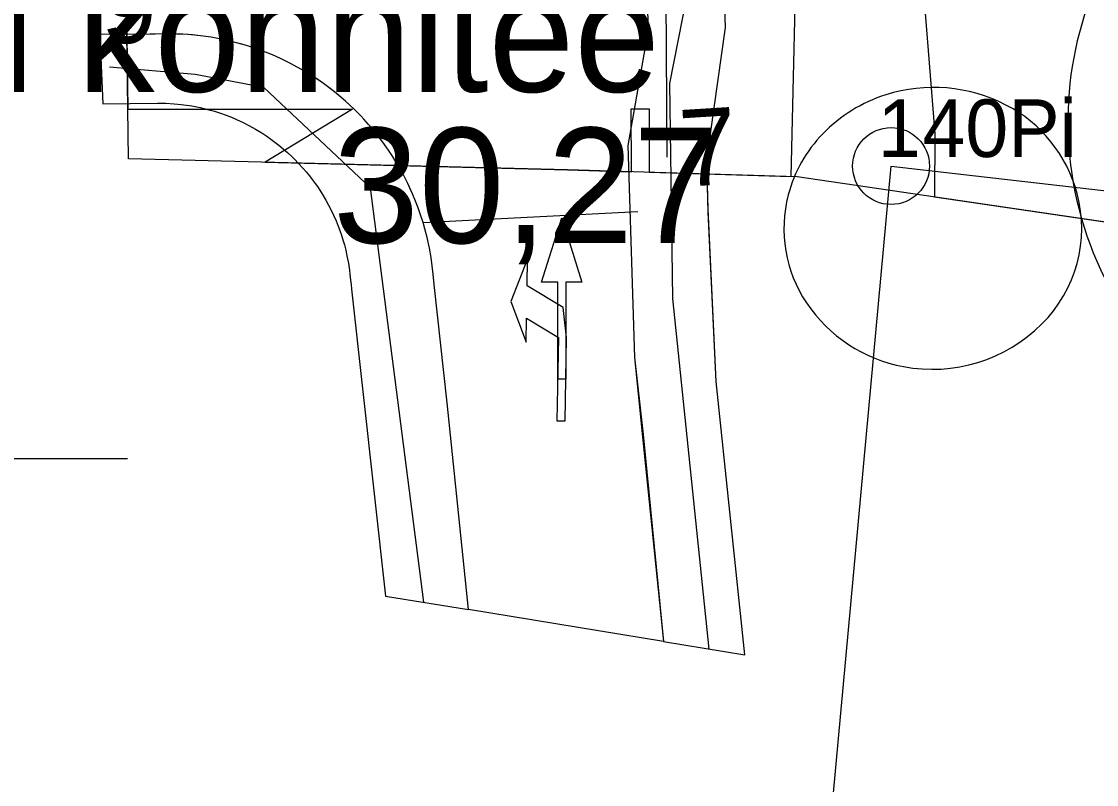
# Model space of a CAD drawing. Extents: x 738423 to 738903, y 6589762 to 6590172.
# Drawn here: x 738562.92 to 738590.9, y 6589849.85 to 6589869.71 of the extents above; entities that cross this region are included whole.
import ezdxf

# ---------------------------------------------------------------- set-up
doc = ezdxf.new("R2010")
doc.units = 0
for name, color, linetype in [('_1927_koordin_punktid_nr', 7, 'Continuous'), ('_1927_krundi_piir', 7, 'Continuous'), ('_a_olol_maapind', 7, 'Continuous'), ('a_', 7, 'Continuous'), ('a_dendro_III_vk_puu', 7, 'Continuous'), ('a_dendro_IV_vk_puu', 7, 'Continuous'), ('a_dendro_puu_nr', 7, 'Continuous'), ('Default', 7, 'Continuous'), ('plan_ala', 7, 'Continuous'), ('v_dp_jalak_liikumine', 7, 'Continuous'), ('v_olol_kitsendus_tehnov', 7, 'Continuous'), ('v_olol_sõidusuunad', 7, 'Continuous'), ('v_olol_transp_jjt_jalg', 7, 'Continuous'), ('v_olol_transp_tee', 7, 'Continuous')]:
    doc.layers.add(name, color=color, linetype=linetype)

# ---------------------------------------------------------------- blocks, each defined once
blk = doc.blocks.new('_U589')
at = {"layer": 'Default'}
for centre, radius, start, end in [((-3.0332052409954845e-05, -0.002338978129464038), 0.01836532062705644, 93.86605779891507, 141.50719662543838), ((-4.742218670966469e-05, -0.0020860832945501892), 0.018111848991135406, 48.095809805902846, 93.86605779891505), ((0.00495080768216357, 0.003483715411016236), 0.010628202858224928, 347.0797159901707, 48.09580980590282), ((-0.006053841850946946, 0.0024511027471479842), 0.01066937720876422, 141.5071966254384, 205.50153110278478), ((0.003081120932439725, 0.003912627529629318), 0.012546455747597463, 307.30050710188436, 347.0797159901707), ((-0.004183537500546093, 0.0033432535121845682), 0.012741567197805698, 205.50153110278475, 244.5264522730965), ((-0.0011840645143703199, 0.009511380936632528), 0.019584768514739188, 275.69820016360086, 307.30050710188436), ((-0.0011946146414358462, 0.009617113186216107), 0.019691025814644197, 244.52645227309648, 275.69820016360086)]:
    blk.add_arc(centre, radius, start, end, dxfattribs=at)
blk = doc.blocks.new('_U590')
at = {"layer": 'Default'}
for centre, radius, start, end in [((-0.0016871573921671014, -0.001799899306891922), 0.00692826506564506, 79.6495714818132, 128.1559824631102), ((-0.0017312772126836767, -0.002041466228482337), 0.007173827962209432, 50.05210261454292, 79.6495714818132), ((-0.0011461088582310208, -0.002488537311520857), 0.007804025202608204, 128.15598246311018, 173.69638815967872), ((-0.0022149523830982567, -0.0026189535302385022), 0.007927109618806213, 21.92646920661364, 50.052102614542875), ((-0.002480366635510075, -0.0027257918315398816), 0.008213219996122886, 337.0064535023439, 21.92646920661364), ((-0.0008438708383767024, -0.0025219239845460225), 0.0081081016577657, 173.69638815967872, 229.18747812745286), ((-0.0016395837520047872, -0.0030825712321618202), 0.007299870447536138, 289.19482591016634, 337.0064535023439), ((-0.0015500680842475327, -0.0033396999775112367), 0.0070276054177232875, 229.1874781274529, 289.1948259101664)]:
    blk.add_arc(centre, radius, start, end, dxfattribs=at)

msp = doc.modelspace()

# ---------------------------------------------------------------- linework, layer by layer
at = {"layer": '_1927_koordin_punktid_nr'}
msp.add_circle((738585.555873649, 6589865.948799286), 0.9999999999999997, dxfattribs=at)
at = {"layer": '_1927_krundi_piir'}
msp.add_line((738585.5558736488, 6589865.948799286), (738628.4452282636, 6589861.013076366), dxfattribs=at)
msp.add_lwpolyline([(738576.2192239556, 6589785.5837573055), (738579.4444540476, 6589812.005081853), (738580.8623448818, 6589823.675676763), (738581.9676572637, 6589832.801945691), (738582.8075223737, 6589836.050380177), (738585.555873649, 6589865.948799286)], dxfattribs=at)
at = {"layer": 'a_'}
for p, q in [((738579.7240658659, 6589866.182764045), (738579.6493548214, 6589878.283505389)), ((738539.292371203, 6589858.339526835), (738565.6824737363, 6589858.339526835))]:
    msp.add_line(p, q, dxfattribs=at)
at = {"layer": 'Default'}
msp.add_lwpolyline([(738579.014, 6589875.606999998), (738579.2310000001, 6589869.493000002), (738578.7019999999, 6589866.485), (738578.8769999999, 6589860.961), (738579.632728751, 6589853.570491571), (738581.7524627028, 6589853.223434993), (738581.004, 6589860.344), (738580.7943856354, 6589864.828322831), (738580.7600000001, 6589866.106), (738581.2509999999, 6589869.558000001), (738581.073, 6589874.656)], dxfattribs=at)
at = {"layer": 'plan_ala'}
msp.add_lwpolyline([(738772.2221966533, 6589837.873120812), (738583.11, 6589865.669999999), (738583.11, 6589865.669999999), (738577.13, 6589865.85), (738565.7035831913, 6589866.139410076), (738565.4500000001, 6589885.77), (738564.4932191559, 6589941.052825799), (738581.9, 6589941.1499999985), (738615.11, 6589942.169999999), (738650.0499999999, 6589943.319999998), (738691.2690631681, 6589944.800325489), (738696.0901513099, 6589944.851371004), (738713.89, 6589945.129999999), (738703.51, 6589987.789999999), (738752.8799999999, 6590000.39), (738783.1408503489, 6590007.463828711), (738767.5688789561, 6589951.87996157)], close=True, dxfattribs=at)
at = {"layer": 'v_dp_jalak_liikumine'}
msp.add_line((738573.3744552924, 6589864.476376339), (738578.9635974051, 6589864.765707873), dxfattribs=at)
for points in [[(738580.8222069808, 6589853.375742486), (738579.8731274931, 6589862.502301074), (738579.7948247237, 6589868.094183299), (738580.455907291, 6589871.452329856), (738579.9085136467, 6589877.0110812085), (738579.325053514, 6589882.302804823), (738578.6922566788, 6589901.835364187), (738578.2534358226, 6589923.78491095), (738577.7643827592, 6589940.522382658), (738578.0100246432, 6589944.392285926), (738576.7151896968, 6589950.204053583)], [(738573.3920130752, 6589854.592261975), (738572.0100758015, 6589865.3794858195), (738569.2273186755, 6589867.989252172), (738567.4426170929, 6589868.3328705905), (738565.2094625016, 6589868.519053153)]]:
    msp.add_lwpolyline(points, dxfattribs=at)
at = {"layer": 'v_olol_kitsendus_tehnov'}
for points in [[(738585.9107412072, 6589876.549701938), (738586.6978541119, 6589866.78586143), (738586.6888850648, 6589865.143953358), (738591.9451522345, 6589864.37135473)], [(738565.6046055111, 6589873.801551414), (738565.6869613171, 6589867.426156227), (738571.5336106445, 6589867.43149151), (738569.2669358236, 6589866.049156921), (738577.1299999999, 6589865.8500000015), (738578.7979030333, 6589865.799795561), (738578.7947118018, 6589867.438117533), (738579.2613153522, 6589867.438543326), (738579.2582244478, 6589865.7859397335), (738582.957333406, 6589865.674595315), (738583.1203691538, 6589872.717573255)]]:
    msp.add_lwpolyline(points, dxfattribs=at)
at = {"layer": 'v_olol_sõidusuunad'}
for points in [[(738577.5114060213, 6589862.922177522), (738577.0914062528, 6589862.922619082), (738577.0887569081, 6589860.402620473), (738576.8787570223, 6589860.402841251), (738576.8814063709, 6589862.92283986), (738576.4614066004, 6589862.923281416), (738576.9881725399, 6589864.602728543)], [(738576.0948898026, 6589863.532438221), (738575.6548239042, 6589862.420169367), (738576.0558806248, 6589861.362788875), (738576.0672058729, 6589861.992687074), (738576.8982616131, 6589861.487665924), (738576.8592524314, 6589859.318016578), (738577.0692184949, 6589859.314241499), (738577.1082276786, 6589861.483890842), (738577.017243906, 6589862.264402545), (738576.0823061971, 6589862.832551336)]]:
    msp.add_lwpolyline(points, close=True, dxfattribs=at)
at = {"layer": 'v_olol_transp_jjt_jalg'}
msp.add_lwpolyline([(738579.0140000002, 6589875.607), (738579.2310000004, 6589869.493000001), (738578.7019999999, 6589866.484999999), (738578.877, 6589860.960999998), (738579.1017005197, 6589858.959409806), (738579.632728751, 6589853.57049157), (738581.7524627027, 6589853.223434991), (738581.004, 6589860.343999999), (738580.798, 6589864.750999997), (738580.7599999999, 6589866.106), (738581.2509999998, 6589869.558000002), (738581.073, 6589874.656)], dxfattribs=at)
msp.add_lwpolyline([(738572.3946838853, 6589854.7555511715), (738574.5591009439, 6589854.401178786), (738574.004, 6589859.782999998), (738573.6600000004, 6589862.862), (738573.6395755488, 6589863.131091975), (738573.6147114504, 6589863.353287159), (738573.5837051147, 6589863.568169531), (738573.5398720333, 6589863.813214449), (738573.479722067, 6589864.0881818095), (738573.4215000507, 6589864.3137841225), (738573.3744552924, 6589864.476376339), (738573.3111121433, 6589864.6748357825), (738573.2448793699, 6589864.86300471), (738573.1786534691, 6589865.035672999), (738573.0989096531, 6589865.227154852), (738573.04262213, 6589865.353333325), (738572.9757975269, 6589865.4949414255), (738572.852584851, 6589865.736401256), (738572.7881642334, 6589865.854004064), (738572.6672425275, 6589866.061245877), (738572.5789254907, 6589866.202866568), (738572.4713293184, 6589866.365743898), (738572.3253519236, 6589866.571885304), (738572.1786709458, 6589866.764068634), (738572.0499184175, 6589866.921946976), (738571.9538094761, 6589867.03386917), (738571.8311355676, 6589867.170000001), (738571.7540000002, 6589867.251999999), (738571.5939999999, 6589867.42), (738571.4575932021, 6589867.54389603), (738571.355055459, 6589867.637076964), (738571.1835234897, 6589867.784882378), (738571.0680918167, 6589867.879011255), (738570.9216031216, 6589867.992681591), (738570.7808902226, 6589868.096115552), (738570.6347633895, 6589868.197892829), (738570.5405588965, 6589868.260602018), (738570.3556464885, 6589868.374174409), (738570.2066602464, 6589868.465681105), (738569.9079593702, 6589868.628036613), (738569.7716900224, 6589868.6945040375), (738569.6659419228, 6589868.746084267), (738569.4534425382, 6589868.840351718), (738569.2770557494, 6589868.910307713), (738569.1559594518, 6589868.958335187), (738568.9883774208, 6589869.01791195), (738568.7749243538, 6589869.08687376), (738568.6236922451, 6589869.129865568), (738568.5181900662, 6589869.159857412), (738568.2873880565, 6589869.21645726), (738568.0740578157, 6589869.261377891), (738567.8551332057, 6589869.300242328), (738567.5852627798, 6589869.338247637), (738567.3690840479, 6589869.36091705), (738567.1188560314, 6589869.378618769), (738566.9526499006, 6589869.3853465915), (738566.7632089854, 6589869.388136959), (738566.6194704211, 6589869.387216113), (738566.2617180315, 6589869.384185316), (738564.9604277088, 6589869.373161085), (738565.0397227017, 6589867.569216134), (738566.4576086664, 6589867.586150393), (738566.6749656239, 6589867.583258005), (738566.8955249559, 6589867.570641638), (738567.0760495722, 6589867.55300772), (738567.3583810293, 6589867.512055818), (738567.5766583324, 6589867.468983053), (738567.7619819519, 6589867.424388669), (738567.9448603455, 6589867.372947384), (738568.1019275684, 6589867.322687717), (738568.2531859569, 6589867.268800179), (738568.3838190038, 6589867.217782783), (738568.5203121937, 6589867.15988506), (738568.6905623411, 6589867.08081851), (738568.852538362, 6589866.9981868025), (738569.0166993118, 6589866.906638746), (738569.1751405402, 6589866.810355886), (738569.309234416, 6589866.722380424), (738569.4808044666, 6589866.600484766), (738569.6232108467, 6589866.490702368), (738569.7363210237, 6589866.3974643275), (738569.8436929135, 6589866.303612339), (738569.9671767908, 6589866.188704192), (738570.0359672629, 6589866.121201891), (738570.1273440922, 6589866.027364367), (738570.2555975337, 6589865.886901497), (738570.3343811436, 6589865.795032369), (738570.416, 6589865.694891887), (738570.4890914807, 6589865.600518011), (738570.5673997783, 6589865.493975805), (738570.6229726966, 6589865.414618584), (738570.7329121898, 6589865.247255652), (738570.8431480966, 6589865.063240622), (738570.916, 6589864.930883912), (738571.0006800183, 6589864.763904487), (738571.0452007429, 6589864.66937624), (738571.1092237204, 6589864.523585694), (738571.1641554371, 6589864.387311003), (738571.2081053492, 6589864.2690667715), (738571.2483489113, 6589864.151904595), (738571.2885087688, 6589864.024386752), (738571.3256891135, 6589863.894202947), (738571.3600628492, 6589863.760033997), (738571.3932952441, 6589863.61270181), (738571.4092725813, 6589863.533332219), (738571.4299250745, 6589863.419156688), (738571.4576571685, 6589863.233929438), (738571.4695776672, 6589863.135003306), (738571.486699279, 6589862.979918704), (738571.4996085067, 6589862.862989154), (738571.5129433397, 6589862.742204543)], close=True, dxfattribs=at)
at = {"layer": 'v_olol_transp_tee'}
msp.add_lwpolyline([(738579.0140000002, 6589875.607), (738579.2310000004, 6589869.493000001), (738578.7019999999, 6589866.484999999), (738578.877, 6589860.960999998), (738579.097, 6589858.816), (738579.632728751, 6589853.57049157), (738574.5591009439, 6589854.401178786), (738574.004, 6589859.782999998), (738573.6600000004, 6589862.862), (738573.6395755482, 6589863.131091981), (738573.6147114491, 6589863.35328717), (738573.5837051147, 6589863.568169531), (738573.5398720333, 6589863.813214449), (738573.479722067, 6589864.0881818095), (738573.4215000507, 6589864.3137841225), (738573.3744552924, 6589864.476376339), (738573.3111121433, 6589864.6748357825), (738573.2448793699, 6589864.86300471), (738573.1786534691, 6589865.035672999), (738573.0989096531, 6589865.227154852), (738572.9757975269, 6589865.4949414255), (738572.8525848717, 6589865.736401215), (738572.7266290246, 6589865.96152927), (738572.5789254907, 6589866.202866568), (738572.4713293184, 6589866.365743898), (738572.3253519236, 6589866.571885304), (738572.1786709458, 6589866.764068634), (738572.0499184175, 6589866.921946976), (738571.9538094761, 6589867.03386917), (738571.8311355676, 6589867.170000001), (738571.754, 6589867.251999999), (738571.5877808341, 6589867.42), (738571.355055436, 6589867.637076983), (738571.068091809, 6589867.879011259), (738570.7808902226, 6589868.096115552), (738570.5405588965, 6589868.260602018), (738570.2066602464, 6589868.465681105), (738569.9079594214, 6589868.628036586), (738569.6659419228, 6589868.746084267), (738569.4534425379, 6589868.840351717), (738569.1559594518, 6589868.958335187), (738568.9883774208, 6589869.01791195), (738568.7749244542, 6589869.086873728), (738568.5181900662, 6589869.159857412), (738568.2873880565, 6589869.21645726), (738568.0740578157, 6589869.261377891), (738567.8551331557, 6589869.300242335), (738567.5852627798, 6589869.338247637), (738567.2635901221, 6589869.369492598), (738566.9526499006, 6589869.3853465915), (738566.7632089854, 6589869.388136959), (738566.712, 6589869.388), (738566.6194704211, 6589869.387216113), (738566.3996066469, 6589869.385353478), (738564.9604277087, 6589869.373161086), (738564.4467826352, 6589875.534444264)], dxfattribs=at)

# ---------------------------------------------------------------- block references
at = {"layer": 'a_dendro_III_vk_puu', "xscale": 500.0000000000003, "yscale": 500.0000000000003, "rotation": 85.69234851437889}
msp.add_blockref('_U589', (738598.176, 6589867.216), dxfattribs=at)
at = {"layer": 'a_dendro_IV_vk_puu', "xscale": 500.0000000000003, "yscale": 500.0000000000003, "rotation": 85.69234851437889}
msp.add_blockref('_U590', (738585.397310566, 6589865.227442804), dxfattribs=at)

# ---------------------------------------------------------------- texts
at = {"layer": '_1927_koordin_punktid_nr'}
for s, p in [('9', (738565.0167192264, 6589869.107865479)), ('7', (738580.1129243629, 6589865.404419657))]:
    msp.add_text(s, height=1.9999999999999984, rotation=3.560863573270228, dxfattribs=at).set_placement(p)
at = {"layer": '_a_olol_maapind'}
for s, p in [('olol kõnnitee', (738557.0146249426, 6589867.880322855)), ('30,27', (738571.0321495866, 6589863.94384969))]:
    msp.add_text(s, height=3, dxfattribs=at).set_placement(p)
at = {"layer": 'a_dendro_puu_nr'}
for s, p in [('1', (738585.2096398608, 6589866.182877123)), ('40Pi', (738586.3750559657, 6589866.182877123))]:
    msp.add_text(s, height=1.5, dxfattribs=at).set_placement(p)

doc.saveas('drawing.dxf')
